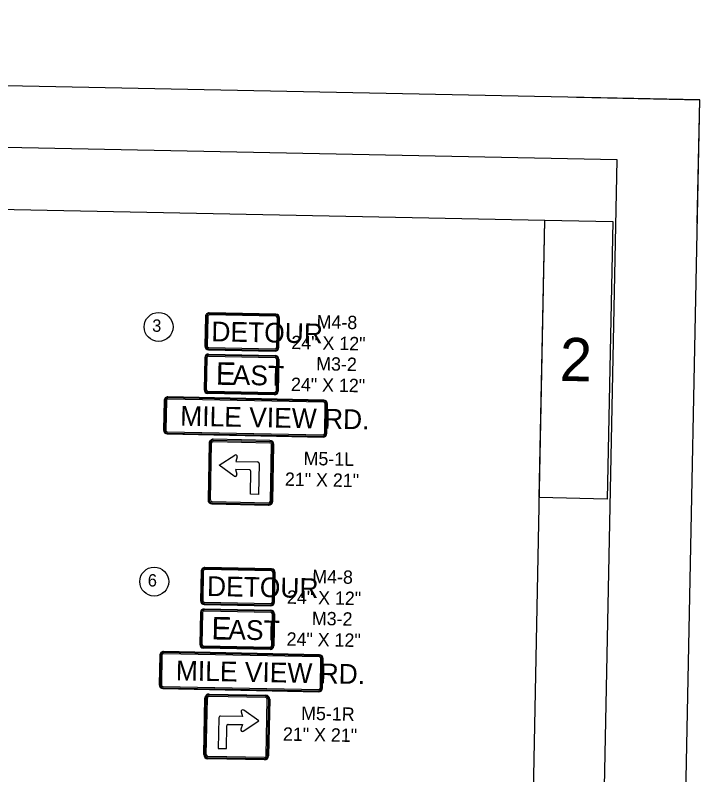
# Model space of a CAD drawing. Extents: x 299354 to 1325680, y 96128 to 228242.
# Drawn here: x 1322906 to 1325680, y 151826 to 154903 of the extents above; entities that cross this region are included whole.
import ezdxf

# ---------------------------------------------------------------- set-up
doc = ezdxf.new("R2010")
doc.units = 0
for name, color, linetype in [('CA-TEXT', 7, 'Continuous'), ('P_SGN_Cell', 7, 'Continuous'), ('PLT_Sheet_Border', 7, 'Continuous'), ('PLT_Sheet_Info', 7, 'Continuous')]:
    doc.layers.add(name, color=color, linetype=linetype)

msp = doc.modelspace()

# ---------------------------------------------------------------- linework, layer by layer
at = {"layer": 'CA-TEXT'}
for centre in [(1323487.2, 153640.4), (1323469.5, 152608.7)]:
    msp.add_circle(centre, 58.6, dxfattribs=at)
at = {"layer": 'P_SGN_Cell'}
for p, q in [((1323689.3, 153530.5), (1323959.4, 153525.1)), ((1323689.4, 153526.8), (1323959.3, 153521.3)), ((1323674.2, 153515.8), (1323671.6, 153385.8)), ((1323677.9, 153515.7), (1323675.3, 153385.8)), ((1323682.9, 153515.6), (1323680.3, 153385.7)), ((1323689.3, 153521.8), (1323959.2, 153516.3)), ((1323965.4, 153510), (1323962.8, 153380)), ((1323970.4, 153509.9), (1323967.8, 153379.9)), ((1323974.1, 153509.8), (1323971.5, 153379.8)), ((1323956.3, 153368.9), (1323686.3, 153374.3)), ((1323956.2, 153365.1), (1323686.3, 153370.5)), ((1323956.4, 153373.9), (1323686.4, 153379.3)), ((1323938.3, 153180.9), (1323708.7, 153185.5)), ((1323692, 153169.4), (1323687.4, 152939.8)), ((1323691.7, 152939.7), (1323696.4, 153169.3)), ((1323697.2, 152939.6), (1323701.8, 153169.2)), ((1323708.5, 153175.7), (1323938.2, 153171)), ((1323708.6, 153181.1), (1323938.3, 153176.5)), ((1323940, 152934.7), (1323944.6, 153164.3)), ((1323945.4, 152934.6), (1323950.1, 153164.2)), ((1323949.8, 152934.5), (1323954.4, 153164.1)), ((1323732.8, 153080), (1323795.6, 153121.3)), ((1323805.4, 153113.8), (1323799.4, 153095.1)), ((1323799.4, 153095.1), (1323888.5, 153093.3)), ((1323793.9, 153036.2), (1323732.8, 153080)), ((1323856.1, 153061.1), (1323798.7, 153062.3)), ((1323798.7, 153062.3), (1323804, 153043.3)), ((1323894.9, 153086.6), (1323892.4, 152961.9)), ((1323859.6, 152962.6), (1323861.4, 153055.5)), ((1323892.4, 152961.9), (1323859.6, 152962.6)), ((1323703.4, 152923.1), (1323933.1, 152918.4)), ((1323703.5, 152927.4), (1323933.2, 152922.8)), ((1323703.6, 152932.9), (1323933.3, 152928.3)), ((1323656.5, 152484.1), (1323653.9, 152354.1)), ((1323660.3, 152484), (1323657.7, 152354.1)), ((1323665.3, 152483.9), (1323662.7, 152354)), ((1323671.6, 152498.8), (1323941.8, 152493.4)), ((1323671.6, 152490.1), (1323941.6, 152484.6)), ((1323671.7, 152495.1), (1323941.7, 152489.6)), ((1323947.7, 152478.2), (1323945.1, 152348.3)), ((1323952.7, 152478.1), (1323950.1, 152348.2)), ((1323956.5, 152478.1), (1323953.8, 152348.1)), ((1323938.5, 152333.4), (1323668.6, 152338.8)), ((1323938.6, 152337.2), (1323668.7, 152342.6)), ((1323938.7, 152342.2), (1323668.8, 152347.6)), ((1323921.2, 152138.9), (1323691.5, 152143.5)), ((1323921.3, 152144.3), (1323691.6, 152148.9)), ((1323691.7, 152153.3), (1323921.4, 152148.7)), ((1323670.4, 151907.6), (1323675, 152137.2)), ((1323674.7, 151907.5), (1323679.4, 152137.2)), ((1323680.2, 151907.4), (1323684.8, 152137)), ((1323923, 151902.5), (1323927.6, 152132.2)), ((1323928.4, 151902.4), (1323933.1, 152132)), ((1323937.4, 152132), (1323932.8, 151902.3)), ((1323821.8, 152081), (1323827.1, 152062)), ((1323893, 152044.2), (1323832, 152088.1)), ((1323731.4, 152057.3), (1323728.8, 151932.7)), ((1323827.1, 152062), (1323738, 152063.8)), ((1323761.7, 151932), (1323763.5, 152025)), ((1323769.1, 152030.3), (1323826.5, 152029.2)), ((1323826.5, 152029.2), (1323820.4, 152010.4)), ((1323830.2, 152002.9), (1323893, 152044.2)), ((1323728.8, 151932.7), (1323761.7, 151932)), ((1323916.2, 151890.6), (1323686.5, 151895.2)), ((1323916.3, 151896.1), (1323686.6, 151900.7)), ((1323916.1, 151886.2), (1323686.4, 151890.9))]:
    msp.add_line(p, q, dxfattribs=at)
for points in [[(1323677.3, 153683), (1323674.9, 153563)], [(1323681.1, 153682.9), (1323678.6, 153562.9)], [(1323686, 153682.8), (1323683.6, 153562.8)], [(1323962.4, 153683.5), (1323692.4, 153688.9)], [(1323962.5, 153688.5), (1323692.5, 153693.9)], [(1323962.5, 153692.2), (1323692.6, 153697.6)], [(1323966.1, 153557.1), (1323968.5, 153677.1)], [(1323971.1, 153557), (1323973.5, 153677)], [(1323974.8, 153556.9), (1323977.2, 153676.9)], [(1323689.8, 153556.4), (1323959.7, 153551)], [(1323689.6, 153547.7), (1323959.5, 153542.2)], [(1323689.7, 153551.4), (1323959.6, 153546)], [(1323509.8, 153342), (1323507.4, 153222)], [(1323513.6, 153341.9), (1323511.2, 153221.9)], [(1323518.6, 153341.8), (1323516.2, 153221.8)], [(1324156.3, 153335.2), (1323525, 153347.9)], [(1324156.4, 153340.2), (1323525.1, 153352.9)], [(1324156.5, 153344), (1323525.2, 153356.9)], [(1324160, 153208.9), (1324162.5, 153328.8)], [(1324165, 153208.8), (1324167.5, 153328.7)], [(1324168.8, 153208.7), (1324171.2, 153328.7)], [(1323522.3, 153215.4), (1324153.7, 153202.7)], [(1323522.1, 153206.7), (1324154.2, 153194)], [(1323522.2, 153210.4), (1324153.6, 153197.7)], [(1323944.9, 152660.5), (1323674.9, 152665.9)], [(1323944.8, 152656.8), (1323674.9, 152662.2)], [(1323659.6, 152651.2), (1323657.2, 152531.3)], [(1323663.4, 152651.2), (1323661, 152531.2)], [(1323668.4, 152651.1), (1323666, 152531.1)], [(1323944.7, 152651.8), (1323674.8, 152657.2)], [(1323948.4, 152525.4), (1323950.8, 152645.4)], [(1323953.4, 152525.3), (1323955.8, 152645.3)], [(1323957.2, 152525.2), (1323959.6, 152645.2)], [(1323671.9, 152516), (1323941.9, 152510.5)], [(1323672, 152519.7), (1323941.9, 152514.3)], [(1323672.1, 152524.7), (1323942, 152519.3)], [(1324138.9, 152312.3), (1323507.5, 152325.2)], [(1323492.2, 152310.3), (1323489.8, 152190.3)], [(1323495.9, 152310.2), (1323493.5, 152190.2)], [(1323500.9, 152310.1), (1323498.5, 152190.1)], [(1324138.7, 152303.5), (1323507.3, 152316.2)], [(1324138.8, 152308.5), (1323507.4, 152321.2)], [(1324142.4, 152177.2), (1324144.8, 152297.1)], [(1324147.4, 152177.1), (1324149.8, 152297)], [(1324151.1, 152177), (1324153.5, 152297)], [(1323504.5, 152178.7), (1324135.9, 152166)], [(1323504.5, 152175), (1324136.6, 152162.3)], [(1323504.6, 152183.7), (1324136, 152171)]]:
    msp.add_lwpolyline(points, dxfattribs=at)
for centre, radius, start, end in [((1323692.3, 153682.7), 15, 88.8468, 178.8468), ((1323692.3, 153682.7), 11.2, 88.8468, 178.8468), ((1323692.3, 153682.7), 6.25, 88.8468, 178.8468), ((1323692.3, 153682.7), 6.25, 88.8468, 96.1883), ((1323962.2, 153677.2), 6.25, 358.8468, 88.8468), ((1323962.2, 153677.2), 15, 358.8468, 88.8468), ((1323962.2, 153677.2), 11.2, 358.8468, 88.8468), ((1323689.9, 153562.7), 15, 178.8468, 268.8468), ((1323689.9, 153562.7), 11.2, 178.8468, 268.8468), ((1323689.9, 153562.7), 6.25, 178.8468, 268.8468), ((1323959.8, 153557.2), 15, 268.8468, 358.8468), ((1323959.8, 153557.2), 11.2, 268.8468, 358.8468), ((1323959.8, 153557.2), 6.25, 268.8468, 358.8468), ((1323689.2, 153515.5), 15, 89.6119, 178.8462), ((1323689.2, 153515.5), 11.2, 88.8462, 178.8462), ((1323959.1, 153510.1), 15, 358.8462, 88.8462), ((1323689.2, 153515.5), 6.25, 88.8462, 178.8462), ((1323959.1, 153510.1), 6.25, 358.8462, 88.8462), ((1323959.1, 153510.1), 11.2, 358.8462, 88.8462), ((1323686.6, 153385.5), 15, 178.8462, 268.8462), ((1323686.6, 153385.5), 11.2, 178.8462, 268.8462), ((1323686.6, 153385.5), 6.25, 178.8462, 268.8462), ((1323956.5, 153380.1), 15, 268.8462, 358.8462), ((1323956.5, 153380.1), 11.2, 268.8462, 358.8462), ((1323956.5, 153380.1), 6.25, 268.8462, 358.8462), ((1323524.8, 153341.9), 15, 88.8468, 178.8468), ((1323524.8, 153341.7), 11.2, 88.8468, 178.8468), ((1323524.8, 153341.7), 6.25, 88.8468, 178.8468), ((1323599.3, 153340.2), 6.25, 88.8468, 96.1883), ((1324156.2, 153329), 11.2, 358.8468, 88.8468), ((1324156.2, 153329), 15, 358.8468, 88.8468), ((1324156.2, 153329), 6.25, 358.8468, 88.8468), ((1323522.4, 153221.7), 15, 178.8468, 268.8468), ((1323522.4, 153221.7), 11.2, 178.8468, 268.8468), ((1323522.4, 153221.7), 6.25, 178.8468, 268.8468), ((1323708.4, 153169.1), 16.4, 88.8462, 178.8462), ((1324153.8, 153209), 15, 268.8468, 358.8468), ((1324153.8, 153209), 11.2, 268.8468, 358.8468), ((1324153.8, 153209), 6.25, 268.8468, 358.8468), ((1323708.4, 153169.1), 12, 88.8462, 178.8462), ((1323708.4, 153169.1), 6.56, 88.8462, 178.8462), ((1323938, 153164.5), 6.56, 358.8462, 88.8462), ((1323938, 153164.5), 12, 358.8462, 88.8462), ((1323938, 153164.5), 16.4, 358.8462, 88.8462), ((1323799.2, 153115.9), 6.56, 342.0436, 123.3759), ((1323888.3, 153086.7), 6.56, 358.8462, 88.8462), ((1323797.7, 153041.5), 6.56, 234.3166, 15.6488), ((1323856, 153055.6), 5.47, 358.8462, 88.8462), ((1323703.8, 152939.5), 16.4, 178.8462, 268.8462), ((1323703.8, 152939.5), 12, 178.8462, 268.8462), ((1323703.8, 152939.5), 6.56, 178.8462, 268.8462), ((1323933.4, 152934.8), 16.4, 268.8462, 358.8462), ((1323933.4, 152934.8), 12, 268.8462, 358.8462), ((1323933.4, 152934.8), 6.56, 268.8462, 358.8462), ((1323674.6, 152650.9), 15, 88.8468, 178.8468), ((1323674.6, 152650.9), 11.2, 88.8468, 178.8468), ((1323674.6, 152650.9), 6.25, 88.8468, 178.8468), ((1323674.6, 152650.9), 6.25, 88.8468, 96.1883), ((1323944.6, 152645.5), 6.25, 358.8468, 88.8468), ((1323944.6, 152645.5), 11.2, 358.8468, 88.8468), ((1323944.6, 152645.5), 15, 358.8468, 88.8468), ((1323672.2, 152531), 15, 178.8468, 268.8468), ((1323672.2, 152531), 11.2, 178.8468, 268.8468), ((1323672.2, 152531), 6.25, 178.8468, 268.8468), ((1323942.2, 152525.5), 11.2, 268.8468, 358.8468), ((1323942.2, 152525.5), 15, 268.8468, 358.8468), ((1323942.2, 152525.5), 6.25, 268.8468, 358.8468), ((1323671.5, 152483.8), 15, 89.6119, 178.8462), ((1323671.5, 152483.8), 11.2, 88.8462, 178.8462), ((1323671.5, 152483.8), 6.25, 88.8462, 178.8462), ((1323941.5, 152478.4), 6.25, 358.8462, 88.8462), ((1323941.5, 152478.4), 11.2, 358.8462, 88.8462), ((1323941.5, 152478.4), 15, 358.8462, 88.8462), ((1323668.9, 152353.8), 15, 178.8462, 268.8462), ((1323668.9, 152353.8), 11.2, 178.8462, 268.8462), ((1323668.9, 152353.8), 6.25, 178.8462, 268.8462), ((1323507.2, 152310.2), 15, 88.8468, 178.8468), ((1323938.8, 152348.4), 15, 268.8462, 358.8462), ((1323938.8, 152348.4), 11.2, 268.8462, 358.8462), ((1323938.8, 152348.4), 6.25, 268.8462, 358.8462), ((1323507.2, 152310), 11.2, 88.8468, 178.8468), ((1323507.2, 152310), 6.25, 88.8468, 178.8468), ((1323581.6, 152308.5), 6.25, 88.8468, 96.1883), ((1324138.6, 152297.3), 6.25, 358.8468, 88.8468), ((1324138.6, 152297.3), 11.2, 358.8468, 88.8468), ((1324138.6, 152297.3), 15, 358.8468, 88.8468), ((1323504.8, 152190), 15, 178.8468, 268.8468), ((1323504.8, 152190), 11.2, 178.8468, 268.8468), ((1323504.8, 152190), 6.25, 178.8468, 268.8468), ((1324136.1, 152177.3), 15, 268.8468, 358.8468), ((1324136.1, 152177.3), 11.2, 268.8468, 358.8468), ((1324136.1, 152177.3), 6.25, 268.8468, 358.8468), ((1323691.4, 152136.9), 16.4, 88.8462, 178.8462), ((1323691.4, 152136.9), 12, 88.8462, 178.8462), ((1323691.4, 152136.9), 6.56, 88.8462, 178.8462), ((1323921, 152132.3), 6.56, 358.8462, 88.8462), ((1323921, 152132.3), 12, 358.8462, 88.8462), ((1323921, 152132.3), 16.4, 358.8462, 88.8462), ((1323828.1, 152082.7), 6.56, 54.3166, 195.6488), ((1323737.9, 152057.2), 6.56, 88.8462, 178.8462), ((1323769, 152024.9), 5.47, 88.8462, 178.8462), ((1323826.6, 152008.4), 6.56, 162.0436, 303.3759), ((1323686.8, 151907.3), 16.4, 178.8462, 268.8462), ((1323686.8, 151907.3), 12, 178.8462, 268.8462), ((1323686.8, 151907.3), 6.56, 178.8462, 268.8462), ((1323916.4, 151902.7), 16.4, 268.8462, 358.8462), ((1323916.4, 151902.7), 12, 268.8462, 358.8462), ((1323916.4, 151902.7), 6.56, 268.8462, 358.8462)]:
    msp.add_arc(centre, radius, start, end, dxfattribs=at)
at = {"layer": 'PLT_Sheet_Border'}
for points in [[(1308461.6, 143905.4), (1325458.1, 143563.1), (1325679.6, 154560.9), (1308683.1, 154903.2)], [(1308586.6, 144153), (1325133.2, 143819.7), (1325344.6, 154317.6), (1308798, 154650.9)]]:
    msp.add_lwpolyline(points, close=True, dxfattribs=at)
at = {"layer": 'PLT_Sheet_Info'}
for p, q in [((1325179.7, 154571), (1325679.6, 154560.9)), ((1325669.5, 154061), (1325679.6, 154560.9)), ((1309305.4, 154390.6), (1325052.2, 154073.4)), ((1324850.8, 144075.5), (1325052.2, 154073.4))]:
    msp.add_line(p, q, dxfattribs=at)
msp.add_lwpolyline([(1325052.2, 154073.4), (1325327.1, 154067.9), (1325304.5, 152943.1), (1325029.5, 152948.7)], close=True, dxfattribs=at)

# ---------------------------------------------------------------- texts
at = {"layer": 'CA-TEXT'}
for s, p in [('3', (1323460.6, 153621)), ('6', (1323442.9, 152589.2))]:
    msp.add_text(s, height=50, rotation=358.8468, dxfattribs=at).set_placement(p)
at = {"layer": 'P_SGN_Cell'}
for s, height, rotation, p in [('M4-8', 54, 358.8468, (1324126.9, 153634.5)), ('DETOUR', 80, 358.8468, (1323700.4, 153582.3)), ('24" X 12"', 54, 358.8468, (1324024.6, 153550.9)), ('E', 91.4, 358.8462, (1323718.3, 153406.3)), ('M3-2', 54, 358.8462, (1324125.3, 153464.9)), ('AST', 80, 358.8462, (1323786.7, 153406.1)), ('24" X 12"', 54, 358.8462, (1324023, 153381.2)), ('MILE VIEW RD.', 80, 358.8468, (1323574.1, 153240.5)), ('M5-1L', 54, 358.8462, (1324074, 153081.2)), ('21" X 21"', 54, 358.8462, (1323998.5, 152997)), ('M4-8', 54, 358.8468, (1324109.3, 152602.8)), ('DETOUR', 80, 358.8468, (1323682.7, 152550.6)), ('24" X 12"', 54, 358.8468, (1324006.9, 152519.2)), ('M3-2', 54, 358.8462, (1324107.7, 152433.2)), ('E', 91.4, 358.8462, (1323700.6, 152374.6)), ('AST', 80, 358.8462, (1323769, 152374.4)), ('24" X 12"', 54, 358.8462, (1324005.3, 152349.5)), ('MILE VIEW RD.', 80, 358.8468, (1323556.4, 152208.8)), ('M5-1R', 54, 358.8462, (1324064.2, 152048.8)), ('21" X 21"', 54, 358.8462, (1323990.5, 151964.6))]:
    msp.add_text(s, height=height, rotation=rotation, dxfattribs=at).set_placement(p)
at = {"layer": 'PLT_Sheet_Info'}
msp.add_text('2', height=175, rotation=358.8462, dxfattribs=at).set_placement((1325111.1, 153422.1))

doc.saveas('drawing.dxf')
